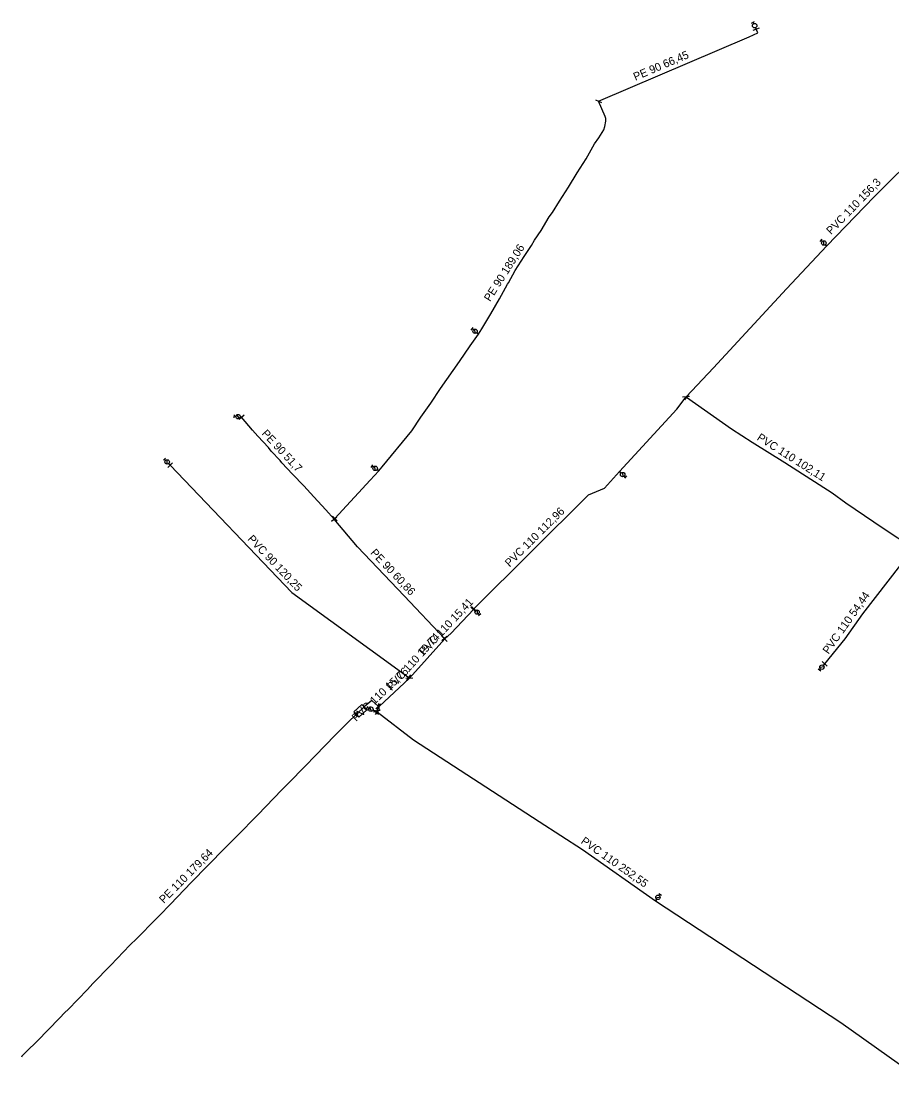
# Model space of a CAD drawing. Extents: x -736619 to -735426, y -1033122 to -1031044.
# Drawn here: x -736618.9 to -736292.8, y -1032730.3 to -1032330 of the extents above; entities that cross this region are included whole.
import ezdxf

# ---------------------------------------------------------------- set-up
doc = ezdxf.new("R2010")
doc.units = 0
for name, color, linetype in [('Vrstva 1', 7, 'Continuous'), ('Vrstva 17', 7, 'Continuous'), ('Vrstva 25', 7, 'Continuous'), ('Vrstva 29', 7, 'Continuous'), ('Vrstva 63', 7, 'Continuous')]:
    doc.layers.add(name, color=color, linetype=linetype)

# ---------------------------------------------------------------- blocks, each defined once
blk = doc.blocks.new('100')
at = {"layer": 'Vrstva 1'}
blk.add_circle((0, 0), 0.127, dxfattribs=at)
blk = doc.blocks.new('133')
at = {"layer": 'Vrstva 1'}
for p, q in [((0.28, 0), (0, 0)), ((0.54, 0.58), (1.7, -0.58)), ((1.94, 0), (2.52, 0)), ((2.52, 0.58), (2.52, -0.58))]:
    blk.add_line(p, q, dxfattribs=at)
blk.add_circle((1.105, 0.003), 0.825, dxfattribs=at)
blk = doc.blocks.new('132')
at = {"layer": 'Vrstva 1'}
for p, q in [((0.3, 0), (0, 0)), ((1.96, 0), (2.52, 0)), ((2.52, 0.58), (2.52, -0.58))]:
    blk.add_line(p, q, dxfattribs=at)
blk.add_circle((1.13, -0.006), 0.825, dxfattribs=at)
blk = doc.blocks.new('147')
at = {"layer": 'Vrstva 1'}
blk.add_line((0, 1.27), (0, -1.27), dxfattribs=at)
blk = doc.blocks.new('111')
at = {"layer": 'Vrstva 1'}
for p, q in [((0.42, 0.72), (-0.83, 0)), ((-0.83, 0), (0.42, -0.72)), ((0.42, -0.72), (0.42, 0.72))]:
    blk.add_line(p, q, dxfattribs=at)

msp = doc.modelspace()

# ---------------------------------------------------------------- linework, layer by layer
at = {"layer": 'Vrstva 17'}
for p, q in [((-736369.87, -1032470.64), (-736369.665, -1032470.784)), ((-736501.687, -1032516.571), (-736501.445, -1032516.315)), ((-736473.52, -1032576.06), (-736460.272, -1032561.42)), ((-736460.272, -1032561.42), (-736460.408, -1032561.275)), ((-736473.725, -1032575.911), (-736473.52, -1032576.06)), ((-736485.001, -1032586.857), (-736485.214, -1032586.639)), ((-736485.74, -1032588.54), (-736486.047, -1032588.935)), ((-736485.543, -1032588.693), (-736485.74, -1032588.54))]:
    msp.add_line(p, q, dxfattribs=at)
for points in [[(-736402.669, -1032359.872), (-736346.212, -1032335.796), (-736343.023, -1032334.282), (-736343.538, -1032332.828)], [(-736261.91, -1032357.61), (-736281.44, -1032377.85), (-736299.4, -1032395.69), (-736313.59, -1032410.41), (-736317.07, -1032414.11), (-736332.24, -1032430.24), (-736359.63, -1032459.8), (-736369.87, -1032470.64)], [(-736501.445, -1032516.315), (-736488.162, -1032501.899), (-736484.95, -1032498.399), (-736483.674, -1032496.944), (-736472.617, -1032483.404), (-736469.2, -1032478.331), (-736465.449, -1032473.004), (-736461.893, -1032467.526), (-736454.768, -1032457.363), (-736450.711, -1032451.57), (-736447.613, -1032447.173), (-736446.429, -1032445.198), (-736443.01, -1032439.548), (-736439.793, -1032433.902), (-736436.797, -1032428.421), (-736436.425, -1032427.935), (-736433.862, -1032423.364), (-736430.465, -1032418.022), (-736427.814, -1032413.999), (-736426.681, -1032411.971), (-736424.148, -1032408.344), (-736421.089, -1032403.237), (-736419.864, -1032401.591), (-736417.316, -1032397.364), (-736413.911, -1032392.148), (-736410.689, -1032386.658), (-736407.318, -1032381.519), (-736404.172, -1032375.809), (-736402.58, -1032373.557), (-736400.682, -1032370.569), (-736400.24, -1032369.317), (-736399.89, -1032367.332), (-736399.924, -1032366.367), (-736400.134, -1032365.619), (-736402.669, -1032359.872)], [(-736449.322, -1032550.131), (-736406.36, -1032507.4), (-736400.37, -1032504.84), (-736394.79, -1032498.7), (-736373.3, -1032475.26), (-736369.87, -1032470.64)], [(-736369.665, -1032470.784), (-736352.83, -1032482.62), (-736345.1, -1032487.61), (-736332.9, -1032495.32), (-736315.17, -1032506.58), (-736310.03, -1032510.36), (-736295.95, -1032519.89), (-736284.67, -1032527.33)], [(-736501.687, -1032516.571), (-736504.836, -1032513.01), (-736509.344, -1032508.148), (-736513.081, -1032504.035), (-736517.254, -1032499.674), (-736521.264, -1032495.352), (-736521.896, -1032494.561), (-736525.241, -1032490.97), (-736526.281, -1032489.676), (-736530.253, -1032485.416), (-736532.27, -1032483.102), (-736536.359, -1032478.239)], [(-736563.14, -1032496.227), (-736517.61, -1032543.99), (-736473.725, -1032575.911)], [(-736460.408, -1032561.275), (-736475.41, -1032545.288), (-736492.892, -1032526.839), (-736501.687, -1032516.571)], [(-736284.824, -1032527.529), (-736303.72, -1032551.93), (-736310.34, -1032561.33), (-736317.93, -1032570.73)], [(-736460.272, -1032561.42), (-736457.85, -1032559.19), (-736449.547, -1032550.365)], [(-736449.547, -1032550.365), (-736449.381, -1032550.19), (-736449.322, -1032550.131)], [(-736473.52, -1032576.06), (-736484.848, -1032586.688), (-736485.001, -1032586.857)], [(-736485.214, -1032586.639), (-736487.635, -1032584.42), (-736490.446, -1032586.856), (-736493.362, -1032589.582)], [(-736485.74, -1032588.54), (-736485.2, -1032587.001), (-736485.001, -1032586.857)], [(-736493.362, -1032589.582), (-736496.589, -1032592.77), (-736501.328, -1032597.451), (-736508.805, -1032605.15), (-736512.482, -1032608.937), (-736513.459, -1032609.943), (-736517.927, -1032614.543), (-736521.261, -1032617.977), (-736530.271, -1032627.256), (-736538.141, -1032635.29), (-736540.67, -1032637.871), (-736542.468, -1032639.707), (-736549.003, -1032646.329), (-736555.229, -1032652.638), (-736563.067, -1032660.806), (-736567.12, -1032665.029), (-736568.482, -1032666.449), (-736575.683, -1032673.647), (-736578.25, -1032676.212), (-736585.397, -1032683.63), (-736592.063, -1032690.55), (-736594.16, -1032692.727), (-736601.376, -1032700.216), (-736602.562, -1032701.447), (-736604.555, -1032703.493), (-736612.921, -1032712.081), (-736616.924, -1032716.039), (-736618.703, -1032717.797), (-736618.881, -1032718.079)], [(-736485.543, -1032588.693), (-736471.99, -1032599.23), (-736424.93, -1032629.8), (-736408.64, -1032640.35), (-736381.3, -1032659.56), (-736311.84, -1032705.2), (-736276.525, -1032730.304)]]:
    msp.add_lwpolyline(points, dxfattribs=at)
at = {"layer": 'Vrstva 25'}
msp.add_lwpolyline([(-736491.304, -1032585.974), (-736494.297, -1032588.776), (-736493.374, -1032589.762), (-736492.452, -1032590.747), (-736489.459, -1032587.945), (-736490.361, -1032586.981), (-736491.304, -1032585.974)], dxfattribs=at)
at = {"layer": 'Vrstva 63'}
for p, q in [((-736343.538, -1032332.828), (-736343.659, -1032332.58)), ((-736536.359, -1032478.239), (-736536.577, -1032478.216)), ((-736394.79, -1032498.7), (-736394.421, -1032499.038)), ((-736317.93, -1032570.73), (-736318.244, -1032571.119)), ((-736381.3, -1032659.56), (-736381.013, -1032659.151))]:
    msp.add_line(p, q, dxfattribs=at)
for points in [[(-736317.07, -1032414.11), (-736317.252, -1032413.938), (-736317.434, -1032413.767)], [(-736447.613, -1032447.173), (-736447.89, -1032446.932), (-736448.052, -1032446.795)], [(-736563.14, -1032496.227), (-736563.318, -1032496.041), (-736563.49, -1032495.86)], [(-736484.95, -1032498.399), (-736485.239, -1032498.165), (-736485.413, -1032498.054)], [(-736449.322, -1032550.131), (-736449.17, -1032550.305), (-736448.933, -1032550.541)], [(-736485.868, -1032588.705), (-736486.34, -1032588.369), (-736486.905, -1032588.185)]]:
    msp.add_lwpolyline(points, dxfattribs=at)

# ---------------------------------------------------------------- block references
at = {"layer": 'Vrstva 25'}
for name, p, xscale, yscale, rotation in [('132', (-736343.659, -1032332.58), 0.9999999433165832, 0.999999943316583, 115.9999999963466), ('133', (-736317.434, -1032413.767), 0.9999999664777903, 0.9999999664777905, 137.00000193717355), ('133', (-736448.052, -1032446.795), 0.9999999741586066, 0.9999999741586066, 140.00000129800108), ('133', (-736536.577, -1032478.216), 1.0011216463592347, 1.0011216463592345, 173.41738977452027), ('133', (-736563.49, -1032495.86), 0.9999999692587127, 0.9999999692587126, 133.99999919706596), ('133', (-736485.413, -1032498.054), 0.9999999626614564, 0.9999999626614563, 147.0000015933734), ('133', (-736394.421, -1032499.038), 0.9999999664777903, 0.9999999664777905, -42.999998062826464), ('133', (-736448.933, -1032550.541), 0.9999999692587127, 0.9999999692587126, -46.00000080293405), ('133', (-736318.244, -1032571.119), 0.9999999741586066, 0.9999999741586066, -129.99999870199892), ('133', (-736486.905, -1032588.185), 1.0335064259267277, 1.033506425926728, 156.95871849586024), ('133', (-736381.013, -1032659.151), 0.9999999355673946, 0.9999999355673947, 55.0000006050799)]:
    msp.add_blockref(name, p, dxfattribs=dict(at, xscale=xscale, yscale=yscale, rotation=rotation))
at = {"layer": 'Vrstva 29'}
for name, p, xscale, yscale, rotation in [('147', (-736343.538, -1032332.828), 0.9999999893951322, 0.9999999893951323, 109.99999905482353), ('147', (-736402.669, -1032359.872), 0.9999999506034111, 0.9999999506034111, 67.99999971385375), ('147', (-736369.87, -1032470.64), 0.9999999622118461, 0.999999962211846, -85.0000001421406), ('147', (-736369.665, -1032470.784), 0.9999999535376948, 0.9999999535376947, -36.000001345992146), ('147', (-736536.359, -1032478.239), 0.9999999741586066, 0.9999999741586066, 129.99999870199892), ('147', (-736563.14, -1032496.227), 0.9999999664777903, 0.9999999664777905, -47.000001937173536), ('147', (-736501.687, -1032516.571), 0.9999999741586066, 0.9999999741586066, -50.000001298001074), ('147', (-736501.445, -1032516.315), 0.9999999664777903, 0.9999999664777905, 47.000001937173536), ('147', (-736449.547, -1032550.365), 0.9999999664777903, 0.9999999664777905, 47.000001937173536), ('147', (-736449.322, -1032550.131), 0.9999999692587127, 0.9999999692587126, -136.00000080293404), ('147', (-736460.408, -1032561.275), 0.9999999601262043, 0.9999999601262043, -48.0000012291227), ('147', (-736460.272, -1032561.42), 0.999999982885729, 0.9999999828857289, 45), ('147', (-736317.93, -1032570.73), 0.9999999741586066, 0.9999999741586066, -129.99999870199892), ('147', (-736473.725, -1032575.911), 0.9999999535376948, 0.9999999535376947, 143.99999865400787), ('147', (-736473.52, -1032576.06), 0.9999999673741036, 0.9999999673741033, 93.99999995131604), ('147', (-736485.214, -1032586.639), 0.9999999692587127, 0.9999999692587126, 136.00000080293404), ('147', (-736485.001, -1032586.857), 0.9999999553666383, 0.9999999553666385, 1.000000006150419), ('111', (-736493.362, -1032589.582), 0.9999999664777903, 0.9999999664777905, -137.00000193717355), ('147', (-736486.047, -1032588.935), 0.9999999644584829, 0.999999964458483, -129.00000106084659), ('147', (-736485.74, -1032588.54), 0.999999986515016, 0.9999999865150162, -74.99999987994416), ('147', (-736485.543, -1032588.693), 0.9999999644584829, 0.999999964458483, -39.000001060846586)]:
    msp.add_blockref(name, p, dxfattribs=dict(at, xscale=xscale, yscale=yscale, rotation=rotation))
at = {"layer": 'Vrstva 63'}
for p, xscale, yscale, rotation in [((-736317.252, -1032413.938), 0.9999999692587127, 0.9999999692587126, -43.999999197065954), ((-736447.89, -1032446.932), 0.9999999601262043, 0.9999999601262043, -41.999998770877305), ((-736563.318, -1032496.041), 0.9999999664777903, 0.9999999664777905, -47.000001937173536), ((-736485.239, -1032498.165), 0.9999999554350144, 0.9999999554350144, -36.99999920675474), ((-736394.606, -1032498.869), 0.9999999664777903, 0.9999999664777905, -42.999998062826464), ((-736449.169, -1032550.306), 0.9999999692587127, 0.9999999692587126, -46.00000080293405), ((-736318.087, -1032570.924), 0.9999999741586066, 0.9999999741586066, -129.99999870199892), ((-736486.341, -1032588.369), 1.0316957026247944, 1.0316957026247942, -23.584588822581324), ((-736381.156, -1032659.356), 0.9999999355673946, 0.9999999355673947, 55.0000006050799)]:
    msp.add_blockref('100', p, dxfattribs=dict(at, xscale=xscale, yscale=yscale, rotation=rotation))

# ---------------------------------------------------------------- texts
for s, height, rotation, p in [('PE 90 66,45', 2.99999, 23.1, (-736388.831, -1032352.232)), ('PVC 110 156,3', 2.99999, 46.05, (-736315.496, -1032410.081)), ('PE 90 189,06', 2.99999, 57.55, (-736443.276, -1032435.188)), ('PE 90 51,7', 3, 312.86, (-736529.057, -1032484.602)), ('PVC 110 102,11', 2.99999, 327.58, (-736343.566, -1032486.649)), ('PVC 110 112,96', 2.99999, 44.85, (-736435.987, -1032534.612)), ('PVC 90 120,25', 2.99999, 313.63, (-736534.323, -1032524.139)), ('PE 90 60,86', 2.99999, 313.46, (-736488.323, -1032529.335)), ('PVC 110 15,41', 2.99999, 46.74, (-736468.004, -1032567.644)), ('PVC 110 54,44', 2.99999, 54.84, (-736316.501, -1032567.297)), ('PVC 110 19,74', 2.99999, 47.86, (-736480.157, -1032581.012)), ('PVC 110 15,76', 2.99999, 43.17, (-736493.431, -1032592.545)), ('PVC 110 252,55', 2.99999, 324.91, (-736409.515, -1032637.781)), ('PE 110 179,64', 2.99999, 45.38, (-736565.472, -1032660.74))]:
    msp.add_text(s, height=height, rotation=rotation, dxfattribs=at).set_placement(p)

doc.saveas('drawing.dxf')
